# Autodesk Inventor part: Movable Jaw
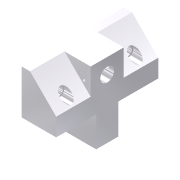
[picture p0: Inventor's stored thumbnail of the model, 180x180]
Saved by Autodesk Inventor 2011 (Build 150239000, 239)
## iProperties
Shininess: 77.0
Length Units: 11269
Angle Units: 11279
Time Units: 11290
Mass Units: 11283
Length Display Precision: 3
Angle Display Precision: 2
Created: 2002-02
Part Number: Movable Jaw
Document SubType Name: Modeling
Designer: ***
Density: 1 g/cm^3
Mass: 56.5592 g
Surface Area: 124.284 cm^2
Volume: 56.5592 cm^3
Density: 0.0
Volumn: 0.0
Area: 0.0
PropertySet Name: Model Information
Control State: 0
Master: False
Checked Out: False
Author: ***
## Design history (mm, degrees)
sketch "Sketch2"
  geometry: L1 (2.39, 41.509)-(2.39, 9.509); L2 (2.39, 9.509)-(-22.61, 9.509); L3 (-22.61, 9.509)-(-22.61, 22.509); L4 (-22.61, 22.509)-(-3.61, 41.509); L5 (-3.61, 41.509)-(2.39, 41.509)
  constraints: 10 end point, 2 parallel, 1 perpendicular, 1 vertical
  dimensions: "d0" = 25 distance of L1.end L2.end; "d2" = 13 distance of L2.end L3.end; "d3" = 32 distance between parallel lines of L5 L2; "d4" = 6 distance of L4.end L1.start
extrude "Extrusion1" new body sketch "Sketch2" stored distance "d5" = 74; taper "d6" = 0 deg
sketch "Sketch3"
  geometry: L1 (-19, 25)-(11, 25); L2 (11, 25)-(11, 49); L3 (11, 49)-(-19, 49); L4 (-19, 49)-(-19, 25); L5 (0, 0)-(13, 0) reference; L6 (-19, 74)-(-19, 0) reference; L7 (11.924, 29)-(35, 29); L8 (35, 29)-(35, 45); L9 (35, 45)-(11.924, 45); L10 (11.924, 45)-(11.924, 29); L11 (13, 74)-(13, 0) reference
  constraints: 16 end point, 4 parallel, 2 horizontal, 2 perpendicular, 1 collinear
  dimensions: "d7" = 24 distance of L3.end L1.start; "d8" = 30 distance of L1.start L1.end; "d9" = 25 distance between parallel lines of L5 L1; "d10" = 16 distance of L7.end L8.end; "d11" = 4 distance between parallel lines of L3 L9; "d12" = 22 distance between parallel lines of L11 L8
extrude "Extrusion2" join sketch "Sketch3" distance "d13" = 25; taper "d14" = 0 deg
sketch "Sketch4"
  geometry: L1 (-19, -25)-(-19, -49) reference; L2 (-19, -49)-(0, -49) reference; 1 further point
  dimensions: "d15" = 11 distance from line of L1 point (-8, -37); "d16" = 12 distance from line of L2 point (-8, -37)
hole "Hole1" sketch "Sketch4" at (-8, -37) diameter "d17" = 10; stored, may be unused: countersink angle "d21" = 82 deg, drill point angle "d23" = 0 deg; dims "d18" = 6, "d19" = 4, "d20" = 2, "d22" = 13
sketch "Sketch5"
  geometry: L1 (-19, -49)-(-19, -74) reference; L2 (0, -74)-(13, -74) reference; 1 further point
  dimensions: "d24" = 14 distance from line of L1 point (-5, -62); "d25" = 12 distance from line of L2 point (-5, -62)
hole "Hole2" sketch "Sketch5" at (-5, -62) diameter "d26" = 6; stored, may be unused: countersink angle "d30" = 82 deg, drill point angle "d32" = 0 deg; dims "d27" = 6, "d28" = 8, "d29" = 10, "d31" = 13
mirror "Mirror1"
sketch "Sketch6"
  geometry: L1 (0, 19)-(0, 0) reference; 1 further point
  dimensions: "d33" = 5 distance from line of L1 point (-5, 8); "d34" = 11 vertical distance of L1.start point (-5, 8)
hole "Hole3" sketch "Sketch6" at (-5, 8) diameter "d35" = 2; stored, may be unused: countersink angle "d39" = 82 deg, drill point angle "d41" = 0 deg; dims "d36" = 6, "d37" = 8, "d38" = 10, "d40" = 13
body "Solid1"
